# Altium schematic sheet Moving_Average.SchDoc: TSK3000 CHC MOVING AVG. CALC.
size A4; Engineer: SHOWELL; Revision: 1.00; SheetNumber: 1; SheetTotal: 2
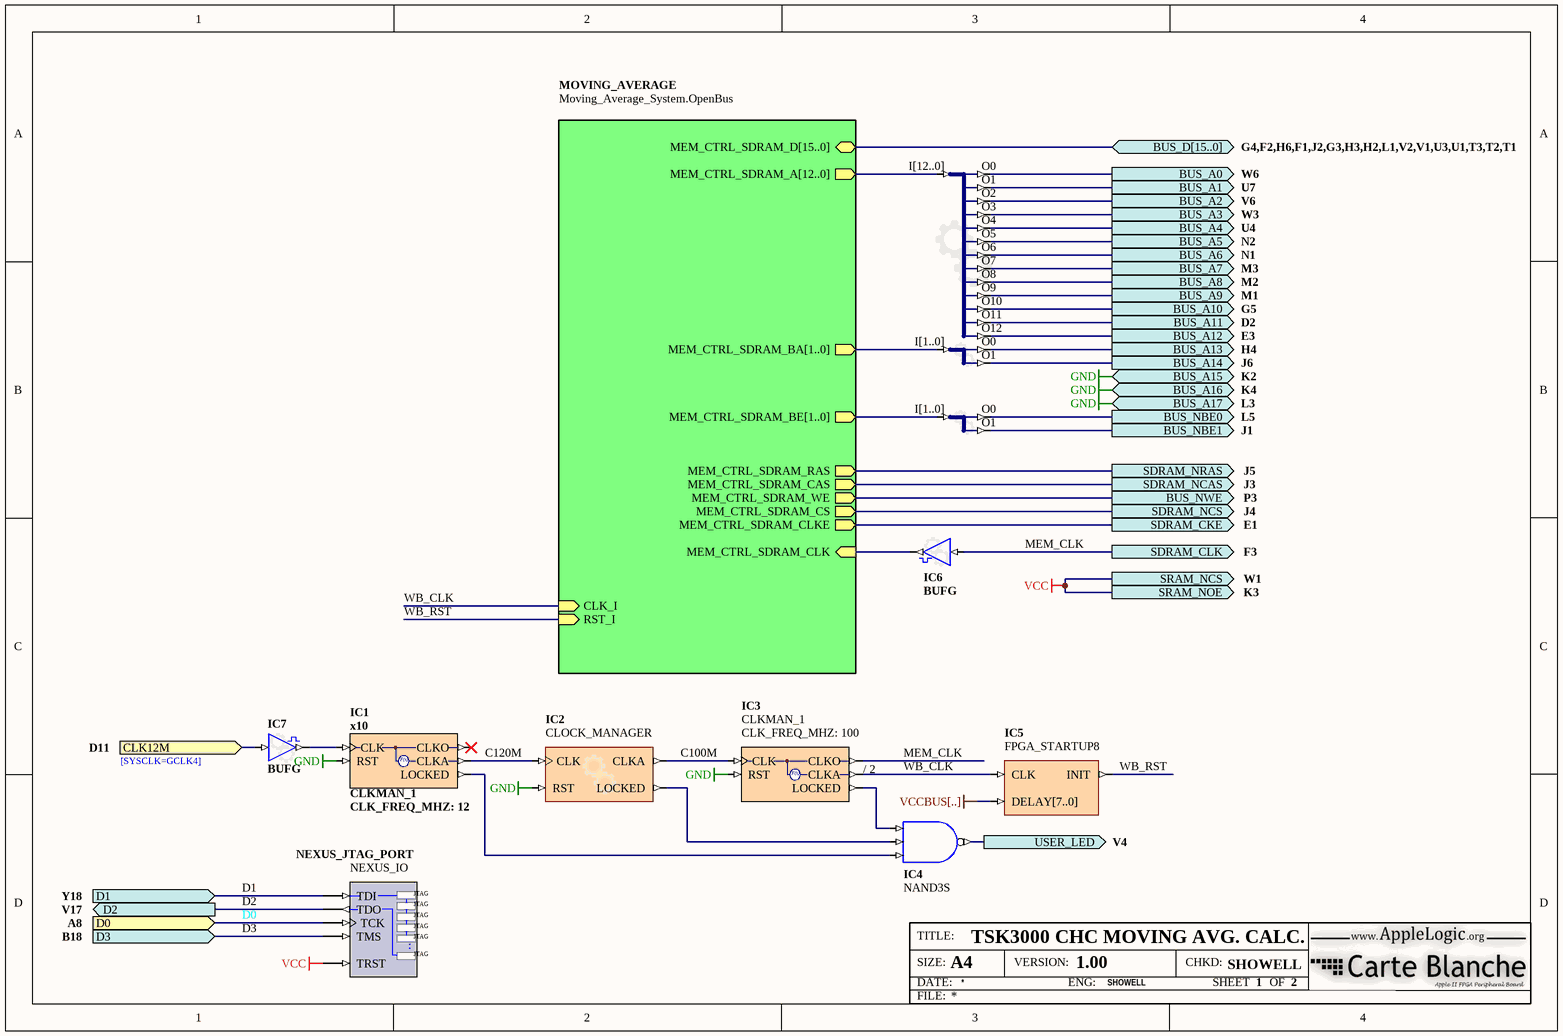
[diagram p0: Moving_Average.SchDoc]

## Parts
IC1  CLKMAN_1  CLK_FREQ_MHZ: 12  ClkA_Operation: x10
IC2  CLOCK_MANAGER
IC3  CLKMAN_1  CLK_FREQ_MHZ: 100  ClkA_Operation: / 2
IC4  NAND3S
IC5  FPGA_STARTUP8
IC6  BUFG
IC7  BUFG
NEXUS_JTAG_PORT  NEXUS_IO
U1011  BUS_JS  (value not drawn)
U1018  BUS_JS  (value not drawn)
U8011  BUS_JS  (value not drawn)

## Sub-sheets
MOVING_AVERAGE = Moving_Average_System.OpenBus: MEM_CTRL_SDRAM_D[15..0] (bidir), MEM_CTRL_SDRAM_A[12..0] (out), MEM_CTRL_SDRAM_BA[1..0] (out), MEM_CTRL_SDRAM_BE[1..0] (out), MEM_CTRL_SDRAM_RAS (out), MEM_CTRL_SDRAM_CAS (out), MEM_CTRL_SDRAM_WE (out), MEM_CTRL_SDRAM_CS (out), MEM_CTRL_SDRAM_CLKE (out), MEM_CTRL_SDRAM_CLK (in), RST_I (in), CLK_I (in)

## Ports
BUS_A0 (out, see W6), BUS_A1 (out, see U7), BUS_A2 (out, see V6), BUS_A3 (out, see W3), BUS_A4 (out, see U4), BUS_A5 (out, see N2), BUS_A6 (out, see N1), BUS_A7 (out, see M3), BUS_A8 (out, see M2), BUS_A9 (out, see M1), BUS_A10 (out, see G5), BUS_A11 (out, see D2), BUS_A12 (out, see E3), BUS_A13 (out, see H4), BUS_A14 (out, see J6), BUS_A15 (out, see K2), BUS_A16 (out, see K4), BUS_A17 (out, see L3), BUS_D[15..0] (bidir, see G4,F2,H6,F1,J2,G3,H3,H2,L1,V2,V1,U3,U1,T3,T2,T1), BUS_NBE0 (out, see L5), BUS_NBE1 (out, see J1), BUS_NWE (out, see P3), CLK12M (in, see D11), D0 (in, see A8), D1 (in, see Y18), D2 (out, see V17), D3 (in, see B18), SDRAM_CKE (out, see E1), SDRAM_CLK (out, see F3), SDRAM_NCAS (out, see J3), SDRAM_NCS (out, see J4), SDRAM_NRAS (out, see J5), SRAM_NCS (out, see W1), SRAM_NOE (out, see K3), USER_LED (out, see V4)

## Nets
GND: IC1.RST IC2.RST IC3.RST ; port BUS_A15, port BUS_A16, port BUS_A17
VCC: NEXUS_JTAG_PORT.TRST ; port SRAM_NOE, port SRAM_NCS
BUS_A0: U1018.O0 ; port BUS_A0
BUS_A1: U1018.O1 ; port BUS_A1
BUS_A2: U1018.O2 ; port BUS_A2
BUS_A3: U1018.O3 ; port BUS_A3
BUS_A4: U1018.O4 ; port BUS_A4
BUS_A5: U1018.O5 ; port BUS_A5
BUS_A6: U1018.O6 ; port BUS_A6
BUS_A7: U1018.O7 ; port BUS_A7
BUS_A8: U1018.O8 ; port BUS_A8
BUS_A9: U1018.O9 ; port BUS_A9
BUS_A10: U1018.O10 ; port BUS_A10
BUS_A11: U1018.O11 ; port BUS_A11
BUS_A12: U1018.O12 ; port BUS_A12
BUS_A13: U8011.O0 ; port BUS_A13
BUS_A14: U8011.O1 ; port BUS_A14
BUS_NBE0: U1011.O0 ; port BUS_NBE0
BUS_NBE1: U1011.O1 ; port BUS_NBE1
BUS_NWE: port BUS_NWE, sheet MOVING_AVERAGE/MEM_CTRL_SDRAM_WE
C100M: IC2.CLKA IC3.CLK
C120M: IC1.CLKA IC2.CLK
CLK12M: IC7.I ; port CLK12M
D0: NEXUS_JTAG_PORT.TCK ; port D0
D1: NEXUS_JTAG_PORT.TDI ; port D1
D2: NEXUS_JTAG_PORT.TDO ; port D2
D3: NEXUS_JTAG_PORT.TMS ; port D3
MEM_CLK: IC3.CLKO IC6.I ; port SDRAM_CLK
SDRAM_CKE: port SDRAM_CKE, sheet MOVING_AVERAGE/MEM_CTRL_SDRAM_CLKE
SDRAM_NCAS: port SDRAM_NCAS, sheet MOVING_AVERAGE/MEM_CTRL_SDRAM_CAS
SDRAM_NCS: port SDRAM_NCS, sheet MOVING_AVERAGE/MEM_CTRL_SDRAM_CS
SDRAM_NRAS: port SDRAM_NRAS, sheet MOVING_AVERAGE/MEM_CTRL_SDRAM_RAS
USER_LED: IC4.O ; port USER_LED
WB_CLK: IC3.CLKA IC5.CLK ; sheet MOVING_AVERAGE/CLK_I
WB_RST: IC5.INIT ; sheet MOVING_AVERAGE/RST_I
NetIC1_CLK: IC1.CLK IC7.O
NetIC1_LOCKED: IC1.LOCKED IC4.I0
NetIC2_LOCKED: IC2.LOCKED IC4.I1
NetIC3_LOCKED: IC3.LOCKED IC4.I2
NetIC6_O: IC6.O ; sheet MOVING_AVERAGE/MEM_CTRL_SDRAM_CLK

Not connected (* = marked no-connect by the designer): IC1 CLKO*; IC5 DELAY[7..0]; U1011 I[1..0]; U1018 I[12..0]; U8011 I[1..0]

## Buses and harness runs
bus port BUS_D[15..0] = sheet MOVING_AVERAGE/MEM_CTRL_SDRAM_D[15..0]

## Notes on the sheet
- [SYSCLK=GCLK4]
- Labels drawn without touching a wire or pin: VCCBUS[..]

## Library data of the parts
IC1 IC3 = CLKMAN_1: Single Operational Output Clock Manager; Clk_Count: 1
IC2 = CLOCKMANAGER: Configurable Clock Manager; ConfiguratorName: GENERIC_CLOCKMANAGER; ConfigurationParameters: {}Version[1.0]{}Option_Configuration[object _1: TClockManagerPersist / VersionMajor [ 0 / VersionMinor [ 0 / InputFreq [ 120.000000000000000000 / InputName [ 'CLK' / OutputTargets [ < / item / Name [ 'CLKA' / OutFreqMin [ 100.000000000000000000 / OutFreqMax [ 100.000000000000000000 / OutPostDivider [ 1.000000000000000000 / end> / OutputDevices [ < / item / Name [ 'Spartan3AN' / Valid [ True / OutputActuals [ < / item / Name [ 'CLK0' / Multipler [ 1.000000000000000000 / Divider [ 1.000000000000000000 / OutFreq [ 120.000000000000000000 / OutputMap [ 1 / end / item / Name [ 'CLK90' / Multipler [ 1.000000000000000000 / Divider [ 1.000000000000000000 / OutPhase [ 90.000000000000000000 / OutFreq [ 120.000000000000000000 / OutputMap [ 2 / end / item / Name [ 'CLK180' / Multipler [ 1.000000000000000000 / Divider [ 1.000000000000000000 / OutPhase [ 180.000000000000000000 / OutFreq [ 120.000000000000000000 / OutputMap [ 3 / end / item / Name [ 'CLK270' / Multipler [ 1.000000000000000000 / Divider [ 1.000000000000000000 / OutPhase [ 270.000000000000000000 / OutFreq [ 120.000000000000000000 / OutputMap [ 4 / end / item / Name [ 'CLK2X' / Multipler [ 2.000000000000000000 / Divider [ 1.000000000000000000 / OutFreq [ 240.000000000000000000 / OutputMap [ 5 / end / item / Name [ 'CLKDV' / Multipler [ 1.000000000000000000 / Divider [ 16.000000000000000000 / OutFreq [ 7.500000000000000000 / OutputMap [ 6 / end / item / Name [ 'CLK2X180' / Multipler [ 1.000000000000000000 / Divider [ 1.000000000000000000 / OutPhase [ 180.000000000000000000 / OutFreq [ 240.000000000000000000 / OutputMap [ 7 / end / item / Name [ 'CLKFX' / Multipler [ 5.000000000000000000 / Divider [ 6.000000000000000000 / OutFreq [ 100.000000000000000000 / OutputMap [ 0 / end / item / Name [ 'CLKFX180' / Multipler [ 1.000000000000000000 / Divider [ 1.000000000000000000 / OutPhase [ 180.000000000000000000 / OutFreq [ 100.000000000000000000 / OutputMap [ 8 / end> / InternalActuals [ <> / CustomVars [ <> / end> / MinInputFreq [ 1.000000000000000000 / MaxInputFreq [ 280.000000000000000000 / MinOutputFreq [ 18.000000000000000000 / MaxOutputFreq [ 210.000000000000000000 / MaxOutputCount [ 9 / end]{}
IC4 = NAND3: 3-Input NAND Gate, Single Pin Version; ArchiveName: GENERIC; XilinxEquivalent: NAND3; FunctionalClass: Logic Primitive; PortSize: 3; VHDLIB_SIM: GENERIC_LIB
IC5 = FPGA_STARTUP8: FPGA Startup With 8 Bit Delay
IC6 IC7 = BUFG: Configurable Global Clock Buffer; ConfiguratorName: GENERIC_BUFFER; ConfigurationParameters: {}Version[1.1]{}SignalCount[1]{}SignalWidth0[1]{}OutputOption0[Global Clock]{}EnableMode[None]{}ShowPinNames[False]{}
NEXUS_JTAG_PORT = NEXUS_JTAG_PORT: Soft Nexus-Chain Connector; NEXUS_JTAG_CONNECTOR: True
U1011 U8011 = BUS_JS: Configurable Bus Joiner/Splitter; ConfiguratorName: GENERIC_BUS_JS; ConfigurationParameters: {}Version[1.1]{}SplitterJoinerType[Splitter]{}SignalCount[2]{}SignalWidth0[1]{}GapBelow0[1000000]{}ConnectionType0[Pin]{}SignalWidth1[1]{}GapBelow1[1000000]{}ConnectionType1[Pin]{}ShowPinNames[True]{}
U1018 = BUS_JS: Configurable Bus Joiner/Splitter; ConfiguratorName: GENERIC_BUS_JS; ConfigurationParameters: {}Version[1.1]{}SplitterJoinerType[Splitter]{}SignalCount[13]{}SignalWidth0[1]{}GapBelow0[1000000]{}ConnectionType0[Pin]{}SignalWidth1[1]{}GapBelow1[1000000]{}ConnectionType1[Pin]{}SignalWidth2[1]{}GapBelow2[1000000]{}ConnectionType2[Pin]{}SignalWidth3[1]{}GapBelow3[1000000]{}ConnectionType3[Pin]{}SignalWidth4[1]{}GapBelow4[1000000]{}ConnectionType4[Pin]{}SignalWidth5[1]{}GapBelow5[1000000]{}ConnectionType5[Pin]{}SignalWidth6[1]{}GapBelow6[1000000]{}ConnectionType6[Pin]{}SignalWidth7[1]{}GapBelow7[1000000]{}ConnectionType7[Pin]{}SignalWidth8[1]{}GapBelow8[1000000]{}ConnectionType8[Pin]{}SignalWidth9[1]{}GapBelow9[1000000]{}ConnectionType9[Pin]{}SignalWidth10[1]{}GapBelow10[1000000]{}ConnectionType10[Pin]{}SignalWidth11[1]{}GapBelow11[1000000]{}ConnectionType11[Pin]{}SignalWidth12[1]{}GapBelow12[1000000]{}ConnectionType12[Pin]{}ShowPinNames[True]{}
